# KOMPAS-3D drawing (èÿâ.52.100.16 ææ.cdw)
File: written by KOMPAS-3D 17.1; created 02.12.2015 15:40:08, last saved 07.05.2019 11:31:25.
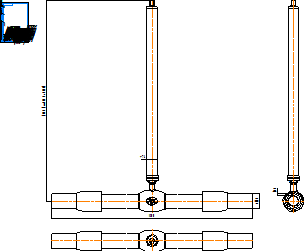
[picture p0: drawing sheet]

Sheet 1: A4, portrait

Title block, sheet 1: name: КШГ.52.100.16 СС; material: Внимание! Данный продукт является объектом авторского права ООО «Торговый Дом АДЛ». / Запрещается изменение, копирование, распространение / (в том числе путем копирования на другие сайты и ресурсы в Интернете) / или любое иное использование информации и объектов без предварительного / согласия правообладателя (ООО «Торговый Дом АДЛ»).; sheets: 1; organisation: ООО "Торговый дом АДЛ"; sheet format: A4; stored path: C:\Users\kka\KOMPAS_Work\Модели кранов для исследований\DN50\С удлинением\КШГ.32.050.40 СС ГЧ _ Шаровой кран БИВАЛ Ду50 Ру4 МПа редуцированный под приварку, с удлинением штока H=1100.cdw; drawn by: Климкович К.А.; drawn by, date: 02.12.15

Views: Вид 1, Проекционный вид 2
Referenced files in C:\Users\kka\KOMPAS_Work\Модели кранов для исследований\DN80\С удлинением\: КШТ.22.080.25 СС.a3d, КШГ.35.065.25 СС.a3d!КШГ.45.065.10 СС!Деталь (локальная).m3d
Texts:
  Klimkovich
  ADL
  (от 380 до 5000)
Dimensions and other numbers on the sheet: 1500; 110; 76; 12,3; 1:1; 1; 02.12.15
